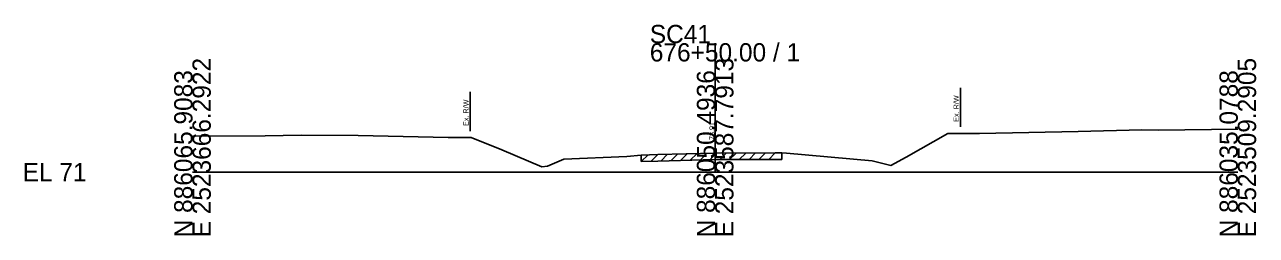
# Model space of a CAD drawing. Extents: x -26 to 183, y -10 to 24021.
# Drawn here: x -25.7 to 162.8, y 8990.3 to 9022.6 of the extents above; entities that cross this region are included whole.
import ezdxf

# ---------------------------------------------------------------- set-up
doc = ezdxf.new("R2010")
doc.units = 0
for name, color, linetype in [('RD_GPK_XS_Cell', 7, 'Continuous'), ('RD_XS_ExGround', 7, 'Continuous'), ('RD_XS_ExPaveRet', 7, 'Continuous'), ('RD_XS_ExRW', 7, 'Continuous'), ('RD_XS_TX_Elev_EX', 7, 'Continuous')]:
    doc.layers.add(name, color=color, linetype=linetype)

msp = doc.modelspace()

# ---------------------------------------------------------------- linework, layer by layer
at = {"layer": 'RD_GPK_XS_Cell'}
for p, q in [((80, 9000), (80, 9019.74)), ((0, 9000), (80, 9000)), ((80, 9000), (160, 9000))]:
    msp.add_line(p, q, dxfattribs=at)
at = {"layer": 'RD_XS_ExGround'}
for p, q in [((120.47, 9005.91), (135.58, 9006.21)), ((135.58, 9006.21), (145.33, 9006.47)), ((145.33, 9006.47), (147.86, 9006.44)), ((147.86, 9006.44), (160, 9006.58)), ((0, 9005.48), (11.1, 9005.54)), ((11.1, 9005.54), (16.65, 9005.63)), ((16.65, 9005.63), (25.37, 9005.59)), ((25.37, 9005.59), (39.15, 9005.3)), ((39.15, 9005.3), (42.67, 9005.28)), ((42.67, 9005.28), (47.37, 9003.41)), ((109.25, 9002.3), (115.61, 9005.91)), ((115.61, 9005.91), (120.47, 9005.91)), ((47.37, 9003.41), (53.46, 9000.78)), ((66.48, 9002.4), (68.7, 9002.6)), ((68.7, 9002.6), (71.21, 9002.67)), ((71.21, 9002.67), (79.9, 9002.91)), ((79.9, 9002.91), (89.2, 9002.94)), ((89.2, 9002.94), (90.21, 9002.94)), ((90.21, 9002.94), (90.92, 9002.88)), ((90.92, 9002.88), (104.01, 9001.71)), ((53.46, 9000.78), (54.35, 9000.92)), ((54.35, 9000.92), (56.82, 9001.96)), ((56.82, 9001.96), (66.48, 9002.4)), ((104.01, 9001.71), (106.91, 9000.99)), ((106.91, 9000.99), (109.25, 9002.3))]:
    msp.add_line(p, q, dxfattribs=at)
at = {"layer": 'RD_XS_ExPaveRet'}
for p, q in [((68.7, 9001.6), (69.73, 9002.63)), ((68.7, 9001.6), (68.7, 9002.6)), ((70.2, 9001.65), (71.23, 9002.68)), ((71.7, 9001.69), (72.73, 9002.72)), ((73.2, 9001.73), (74.23, 9002.76)), ((74.7, 9001.77), (75.73, 9002.8)), ((76.2, 9001.81), (77.23, 9002.84)), ((77.7, 9001.85), (78.73, 9002.88)), ((79.2, 9001.89), (80.22, 9002.91)), ((80.7, 9001.91), (81.7, 9002.92)), ((82.2, 9001.92), (83.2, 9002.92)), ((83.7, 9001.92), (84.7, 9002.92)), ((85.2, 9001.93), (86.2, 9002.93)), ((86.7, 9001.93), (87.7, 9002.93)), ((88.2, 9001.93), (89.2, 9002.94)), ((90.21, 9002.94), (90.21, 9001.94)), ((68.7, 9001.6), (71.21, 9001.67)), ((71.21, 9001.67), (79.9, 9001.91)), ((79.9, 9001.91), (89.2, 9001.94)), ((89.2, 9001.94), (90.21, 9001.94))]:
    msp.add_line(p, q, dxfattribs=at)
at = {"layer": 'RD_XS_ExRW'}
for p, q in [((42.5, 9012.28), (42.5, 9006.28)), ((117.54, 9012.91), (117.54, 9006.91))]:
    msp.add_line(p, q, dxfattribs=at)

# ---------------------------------------------------------------- texts
at = {"layer": 'RD_GPK_XS_Cell'}
for s, p in [('SC41', (70, 9019.74)), ('676+50.00 / 1', (70, 9016.94)), ('EL 71', (-26, 8998.6))]:
    msp.add_text(s, height=2.8, dxfattribs=at).set_placement(p)
for s, p in [('E 2523666.2922', (2.8, 8990)), ('E 2523587.7913', (82.8, 8990)), ('E 2523509.2905', (162.8, 8990)), ('N 886065.9083', (0, 8990)), ('N 886050.4936', (80, 8990)), ('N 886035.0788', (160, 8990))]:
    msp.add_text(s, height=2.8, rotation=90, dxfattribs=at).set_placement(p)
at = {"layer": 'RD_XS_ExRW'}
for p in [(42.25, 9007.06), (117.29, 9007.7)]:
    msp.add_text('Ex. R/W ', height=0.8, rotation=90, dxfattribs=at).set_placement(p)
at = {"layer": 'RD_XS_TX_Elev_EX'}
msp.add_text('73.91', height=0.8, rotation=90, dxfattribs=at).set_placement((79.9, 9004.91))

doc.saveas('drawing.dxf')
